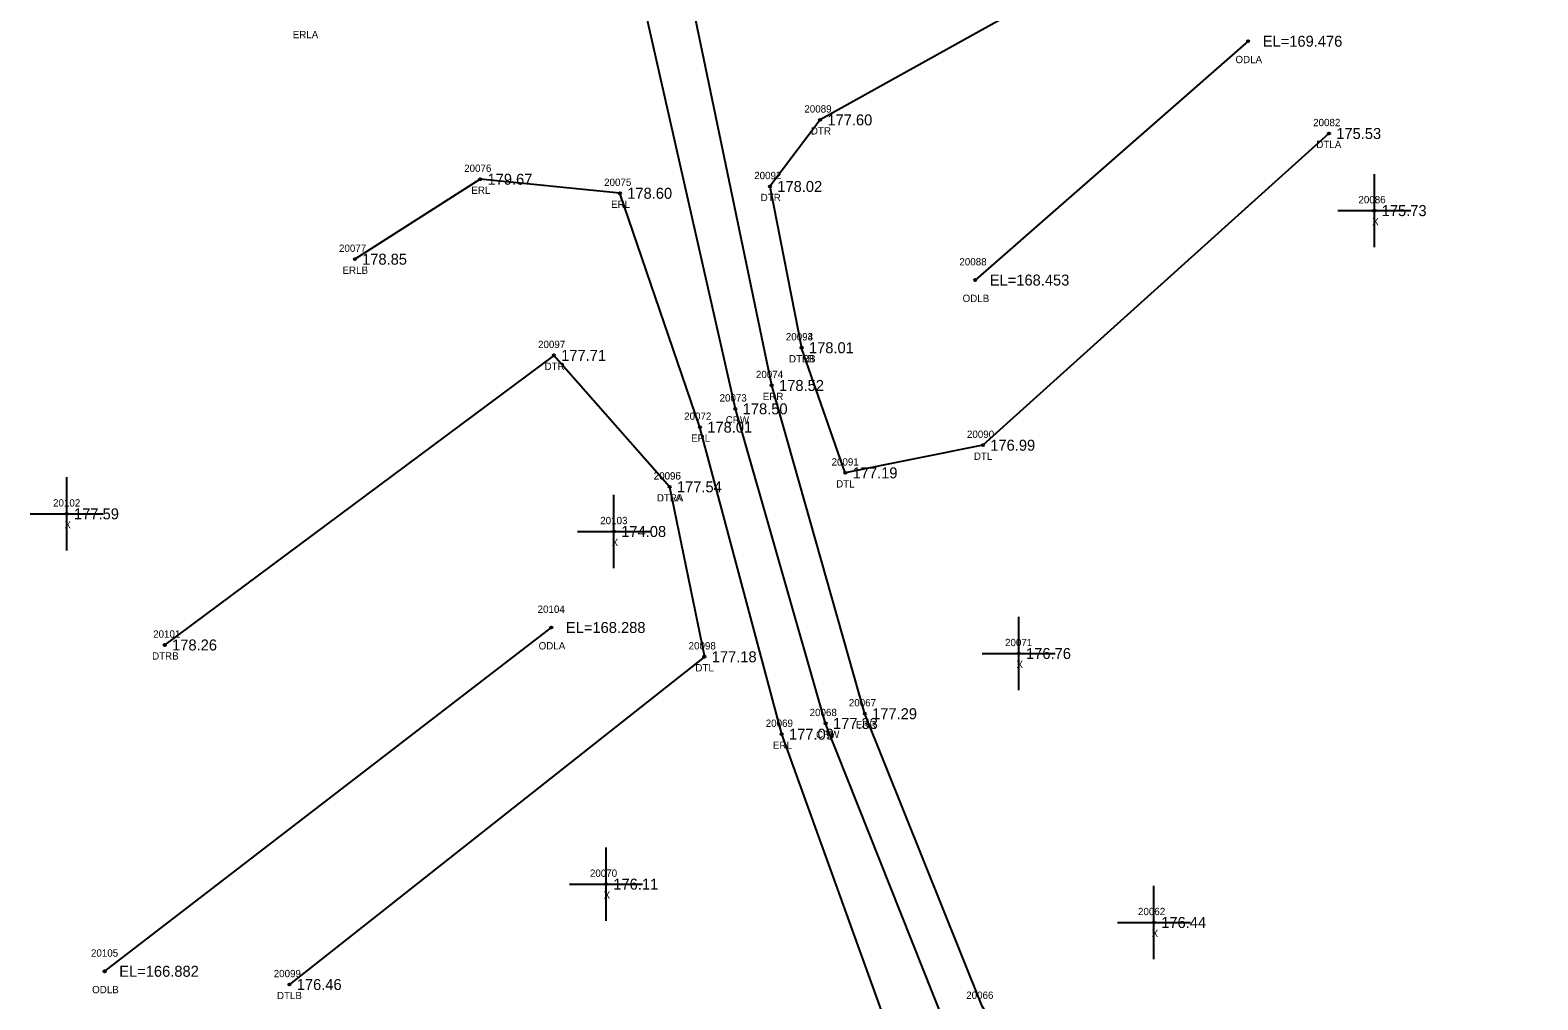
# Model space of a CAD drawing. Extents: x 1970726 to 1971567, y 794829 to 795775.
# Drawn here: x 1970726.2 to 1970932.3, y 795490.3 to 795622.9 of the extents above; entities that cross this region are included whole.
import ezdxf

# ---------------------------------------------------------------- set-up
doc = ezdxf.new("R2010")
doc.units = 0
for name, color, linetype in [('RD_DTM_BkLn1', 7, 'Continuous'), ('RD_EX_H2O', 7, 'Continuous'), ('RD_EX_H2O_txCode', 7, 'Continuous'), ('RD_EX_Misc', 7, 'Continuous'), ('RD_EX_Misc_txCode', 7, 'Continuous'), ('RD_EX_Road', 7, 'Continuous'), ('RD_EX_Road_txCode', 7, 'Continuous'), ('RD_EX_TX_H2O_ELEV', 7, 'Continuous'), ('RD_EX_TX_Misc_ELEV', 7, 'Continuous'), ('RD_EX_TX_Road_ELEV', 7, 'Continuous'), ('RD_HC_Survey_ELEV', 7, 'Continuous'), ('RD_HC_Survey_txCode', 7, 'Continuous'), ('RD_SMD_Locator', 7, 'Continuous')]:
    doc.layers.add(name, color=color, linetype=linetype)

msp = doc.modelspace()

# ---------------------------------------------------------------- linework, layer by layer
at = {"layer": 'RD_DTM_BkLn1'}
msp.add_lwpolyline([(1971548, 794856.6), (1971469.65, 794899.39), (1971398.6, 794938.78), (1971343.49, 794971.52), (1971282.15, 795020.93), (1971214.82, 795076.24), (1971168.26, 795117.15), (1971077.37, 795216.68), (1971014.25, 795285.1), (1970928, 795384.12), (1970874.41, 795450.05), (1970851.19, 795487.2), (1970834.94, 795528.12), (1970822.6, 795571.11), (1970808.56, 795633.3), (1970801.01, 795695.48), (1970787.01, 795762.98)], dxfattribs=at)
at = {"layer": 'RD_EX_H2O'}
for p, q in [((1970892.68, 795621.35), (1970855.37, 795588.71)), ((1970797.44, 795541.23), (1970736.39, 795494.25))]:
    msp.add_line(p, q, dxfattribs=at)
for points in [[(1970883.5, 795638.04), (1970834.18, 795610.6), (1970827.33, 795601.5), (1970831.66, 795579.46)], [(1970903.73, 795608.74), (1970856.44, 795566.14), (1970837.62, 795562.36), (1970831.66, 795579.46)], [(1970813.61, 795560.45), (1970797.79, 795578.42), (1970744.61, 795538.84)], [(1970813.61, 795560.45), (1970818.37, 795537.23), (1970761.65, 795492.44)]]:
    msp.add_lwpolyline(points, dxfattribs=at)
at = {"layer": 'RD_EX_Misc'}
for p, q in [((1970909.94, 795593.2), (1970909.94, 795603.2)), ((1970904.94, 795598.2), (1970914.94, 795598.2)), ((1970731.21, 795551.76), (1970731.21, 795561.76)), ((1970806, 795549.35), (1970806, 795559.35)), ((1970726.21, 795556.76), (1970736.21, 795556.76)), ((1970801, 795554.35), (1970811, 795554.35)), ((1970861.33, 795532.68), (1970861.33, 795542.68)), ((1970856.33, 795537.68), (1970866.33, 795537.68)), ((1970804.92, 795501.16), (1970804.92, 795511.16)), ((1970799.92, 795506.16), (1970809.92, 795506.16)), ((1970879.81, 795495.92), (1970879.81, 795505.92)), ((1970874.81, 795500.92), (1970884.81, 795500.92))]:
    msp.add_line(p, q, dxfattribs=at)
at = {"layer": 'RD_EX_Road'}
for points in [[(1971550.5, 794861.13), (1971472.2, 794904.32), (1971401.49, 794943.08), (1971346.58, 794975.73), (1971286.05, 795024.56), (1971217.92, 795079.41), (1971172.76, 795121.06), (1971082.31, 795221.27), (1971017.96, 795288.13), (1970931.75, 795387.33), (1970878.11, 795452.95), (1970856.35, 795489.48), (1970840.29, 795529.45), (1970827.57, 795574.31), (1970814.81, 795635.62), (1970805.04, 795696.13), (1970791.39, 795763.83)], [(1971543.68, 794851.6), (1971507.7, 794872.08), (1971504.76, 794847.96), (1971494.98, 794846.56), (1971488.18, 794883), (1971469.72, 794893.79), (1971395.92, 794934.76), (1971339.47, 794967.38), (1971278.34, 795016.59), (1971212.1, 795072.1), (1971165.04, 795113.96), (1971074.42, 795213.48), (1971010.42, 795281.48), (1970922.49, 795383.19), (1970882.25, 795365.41), (1970854.66, 795404.07), (1970871.45, 795443.76), (1970844.39, 795483.83), (1970828.93, 795526.65), (1970817.76, 795568.61), (1970806.82, 795600.57), (1970787.72, 795602.49), (1970770.58, 795591.56)]]:
    msp.add_lwpolyline(points, dxfattribs=at)
at = {"layer": 'RD_SMD_Locator'}
for centre in [(1970892.68, 795621.35), (1970834.18, 795610.6), (1970903.73, 795608.74), (1970787.72, 795602.49), (1970827.33, 795601.5), (1970806.82, 795600.57), (1970909.94, 795598.2), (1970770.58, 795591.56), (1970855.37, 795588.71), (1970797.79, 795578.42), (1970831.66, 795579.46), (1970831.66, 795579.46), (1970827.57, 795574.31), (1970822.6, 795571.11), (1970817.76, 795568.61), (1970856.44, 795566.14), (1970837.62, 795562.36), (1970813.61, 795560.45), (1970813.61, 795560.45), (1970731.21, 795556.76), (1970806, 795554.35), (1970797.44, 795541.23), (1970744.61, 795538.84), (1970818.37, 795537.23), (1970861.33, 795537.68), (1970840.29, 795529.45), (1970834.94, 795528.12), (1970828.93, 795526.65), (1970804.92, 795506.16), (1970879.81, 795500.92), (1970736.39, 795494.25), (1970761.65, 795492.44)]:
    msp.add_circle(centre, 0.15, dxfattribs=at)

# ---------------------------------------------------------------- texts
at = {"layer": 'RD_EX_H2O_txCode'}
for s, p in [('ODLA', (1970890.95, 795618.35)), ('20089', (1970832.03, 795611.6)), ('DTR', (1970832.92, 795608.6)), ('20082', (1970901.57, 795609.74)), ('DTLA', (1970902, 795606.74)), ('20092', (1970825.17, 795602.5)), ('DTR', (1970826.06, 795599.5)), ('20088', (1970853.22, 795590.71)), ('ODLB', (1970853.66, 795585.71)), ('20093', (1970829.5, 795580.46)), ('20094', (1970829.5, 795580.46)), ('20097', (1970795.63, 795579.42)), ('DTRB', (1970829.92, 795577.46)), ('DTLB', (1970829.94, 795577.46)), ('DTR', (1970796.52, 795576.42)), ('20090', (1970854.25, 795567.14)), ('20091', (1970835.75, 795563.36)), ('DTL', (1970855.2, 795564.14)), ('20096', (1970811.43, 795561.45)), ('20095', (1970811.45, 795561.45)), ('DTL', (1970836.38, 795560.36)), ('DTRA', (1970811.86, 795558.45)), ('DTLA', (1970811.88, 795558.45)), ('20104', (1970795.57, 795543.23)), ('20101', (1970743.02, 795539.84)), ('ODLA', (1970795.71, 795538.23)), ('20098', (1970816.21, 795538.23)), ('DTRB', (1970742.87, 795536.84)), ('DTL', (1970817.13, 795535.23)), ('20105', (1970734.52, 795496.25)), ('20099', (1970759.5, 795493.44)), ('ODLB', (1970734.68, 795491.25)), ('DTLB', (1970759.94, 795490.44))]:
    msp.add_text(s, height=1, dxfattribs=at).set_placement(p)
at = {"layer": 'RD_EX_Misc_txCode'}
for s, p in [('20086', (1970907.76, 795599.2)), ('X', (1970909.63, 795596.2)), ('20102', (1970729.34, 795557.76)), ('X', (1970730.9, 795554.76)), ('20103', (1970804.13, 795555.35)), ('X', (1970805.69, 795552.35)), ('20071', (1970859.46, 795538.68)), ('X', (1970861.02, 795535.68)), ('20070', (1970802.72, 795507.16)), ('X', (1970804.6, 795504.16)), ('20062', (1970877.63, 795501.92)), ('X', (1970879.5, 795498.92))]:
    msp.add_text(s, height=1, dxfattribs=at).set_placement(p)
at = {"layer": 'RD_EX_Road_txCode'}
for s, p in [('ERLA', (1970762.1, 795621.75)), ('20076', (1970785.53, 795603.49)), ('ERL', (1970786.51, 795600.49)), ('20075', (1970804.66, 795601.57)), ('ERL', (1970805.61, 795598.57)), ('20077', (1970768.42, 795592.56)), ('ERLB', (1970768.9, 795589.56)), ('20074', (1970825.41, 795575.31)), ('ERR', (1970826.34, 795572.31)), ('20072', (1970815.6, 795569.61)), ('ERL', (1970816.55, 795566.61)), ('20067', (1970838.11, 795530.45)), ('20069', (1970826.75, 795527.65)), ('ERR', (1970839.06, 795527.45)), ('ERL', (1970827.73, 795524.65)), ('20066', (1970854.15, 795490.48))]:
    msp.add_text(s, height=1, dxfattribs=at).set_placement(p)
at = {"layer": 'RD_EX_TX_H2O_ELEV'}
for s, p in [('EL=169.476', (1970894.68, 795620.6)), ('177.60', (1970835.18, 795609.85)), ('175.53', (1970904.73, 795607.99)), ('178.02', (1970828.33, 795600.75)), ('EL=168.453', (1970857.37, 795587.96)), ('177.71', (1970798.79, 795577.67)), ('178.01', (1970832.66, 795578.71)), ('178.01', (1970832.66, 795578.71)), ('176.99', (1970857.44, 795565.39)), ('177.19', (1970838.62, 795561.61)), ('177.54', (1970814.61, 795559.7)), ('177.54', (1970814.61, 795559.7)), ('EL=168.288', (1970799.44, 795540.48)), ('178.26', (1970745.61, 795538.09)), ('177.18', (1970819.37, 795536.48)), ('EL=166.882', (1970738.39, 795493.5)), ('176.46', (1970762.65, 795491.69))]:
    msp.add_text(s, height=1.5, dxfattribs=at).set_placement(p)
at = {"layer": 'RD_EX_TX_Misc_ELEV'}
for s, p in [('175.73', (1970910.94, 795597.45)), ('177.59', (1970732.21, 795556.01)), ('174.08', (1970807, 795553.6)), ('176.76', (1970862.33, 795536.93)), ('176.11', (1970805.92, 795505.41)), ('176.44', (1970880.81, 795500.17))]:
    msp.add_text(s, height=1.5, dxfattribs=at).set_placement(p)
at = {"layer": 'RD_EX_TX_Road_ELEV'}
for s, p in [('179.67', (1970788.72, 795601.74)), ('178.60', (1970807.82, 795599.82)), ('178.85', (1970771.58, 795590.81)), ('178.52', (1970828.57, 795573.56)), ('178.01', (1970818.76, 795567.86)), ('177.29', (1970841.29, 795528.7)), ('177.09', (1970829.93, 795525.9))]:
    msp.add_text(s, height=1.5, dxfattribs=at).set_placement(p)
at = {"layer": 'RD_HC_Survey_ELEV'}
for s, p in [('178.50', (1970823.6, 795570.36)), ('177.33', (1970835.94, 795527.37))]:
    msp.add_text(s, height=1.5, dxfattribs=at).set_placement(p)
at = {"layer": 'RD_HC_Survey_txCode'}
for s, p in [('20073', (1970820.44, 795572.11)), ('CRW', (1970821.28, 795569.11)), ('20068', (1970832.75, 795529.12)), ('CRW', (1970833.62, 795526.12))]:
    msp.add_text(s, height=1, dxfattribs=at).set_placement(p)

doc.saveas('drawing.dxf')
